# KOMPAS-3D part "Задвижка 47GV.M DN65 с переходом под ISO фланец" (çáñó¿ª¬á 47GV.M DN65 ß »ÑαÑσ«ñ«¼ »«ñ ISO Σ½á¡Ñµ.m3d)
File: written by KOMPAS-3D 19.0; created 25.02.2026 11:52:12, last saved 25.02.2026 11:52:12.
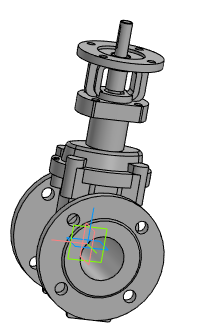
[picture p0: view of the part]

Document properties: Автор: Евгений; Полное имя файла: 47 GV.M DN50\Задвижка 47GV.M DN50 с переходом под ISO фланец.a3d

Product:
- Part/product: Задвижка 47GV.M DN65 с переходом под ISO фланец
    Масса: 17.0429
    Раздел спецификации: Документация
    Форматы листов документа: 2xA3
  - Component: Задвижка с обрезиненным клином DN50. Сборочный чертеж  | designation DR.47GVM.050.16.00.000СБ  | pos. 0  | Масса: 10.0548; Раздел спецификации: Документация; Форматы листов документа: 2xA3; source file: 47GV.M DN65\DR.47GVM.050.16.00.000 СБ - Задвижка с обрезиненным клином DN100.cdw
- Part/product: Задвижка 47GV.M DN65 с переходом под ISO фланец  | designation 01
    Масса: 10.055
  - Component [detail]: Шпиндель  | pos. 5  | Материал: Сталь 20Х13 ГОСТ 5632-2014 (density 7670 kg/m3); Масса: 0.101759; Раздел спецификации: Детали; source file: 47GV.M DN50\DR.47GVM.050.16.00.003 - Шпиндель.cdw, 47GV.M DN65\DR.47GVM.050.16.00.003 - Шпиндель.cdw, 47GV.M DN65\Шпиндель 47GV.M DN50.m3d
  - Component [detail]: Крышка DN65  | pos. 4  | Материал: ВЧ50 ГОСТ 7293-85 (density 7200 kg/m3); Масса: 3.48496; Раздел спецификации: Детали; Форматы листов документа: 2xA3; source file: 47GV.M DN65\DR.47GVM.050.16.00.002 - Крышка.cdw, 47GV.M DN65\DR.47GVM.065.16.00.002 - Крышка.cdw, 47GV.M DN65\Крышка 47GV.M DN50.m3d
  - Component [assembly]: Клин с направляющими  | designation DR.47GVM.050.16.01.000  | pos. 4  | Раздел спецификации: Сборочные единицы; Форматы листов документа: A4; source file: 47GV.M DN65\DR.47GVM.050.16.01.000  - Клин с направляющими.a3d, 47GV.M DN65\DR.47GVM.050.16.01.000  - Клин с направляющими.spw, 47GV.M DN65\DR.47GVM.050.16.01.000  СБ - Клин с направляющими.cdw
  - Component [detail]: Корпус  | designation DR.47GVM.065.16.00.001  | pos. 3  | Материал: ВЧ50 ГОСТ 7293-85 (density 7200 kg/m3); Масса: 11.3996; Раздел спецификации: Детали; Форматы листов документа: 2xA3; source file: 47GV.M DN65\DR.47GVM.050.16.00.001 - Корпус.cdw, 47GV.M DN65\Корпус 47GV.M DN50.m3d
  - Component [detail]: Стойка  | pos. 44  | Материал: ВЧ50 ГОСТ 7293-85 (density 7200 kg/m3); Масса: 1.73762; Раздел спецификации: Детали; Форматы листов документа: 2xA3; source file: 47GV.M DN50\DR.47GVAM.050.16.00.001 - Стойка.cdw, 47GV.M DN65\Стойка DN50.m3d
  - Component [detail]: Удлинитель шпинделя  | pos. 45  | Материал: Сталь 20Х13 ГОСТ 5632-72 (density 7670 kg/m3); Масса: 0.307911; Раздел спецификации: Детали; source file: 47GV.M DN50\DR.47GVAM.050.16.00.002 - Удлинитель шпинделя.cdw, 47GV.M DN65\Удлинитель шпинделя DN50.m3d

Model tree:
1. Операция без истории:1

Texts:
  Точка начала. Х
  Точка начала. Y
  Точка начала. Z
